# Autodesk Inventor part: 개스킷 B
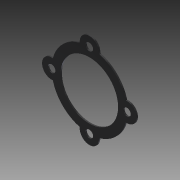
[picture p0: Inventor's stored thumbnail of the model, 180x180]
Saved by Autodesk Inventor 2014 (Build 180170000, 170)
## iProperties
Created: 2020-03
Part Number: 개스킷 B
Material: 고무
Document SubType Name: Modeling
Designer: mduedu
Density: 0.93 g/cm^3
Mass: 1.13966 g
Surface Area: 28.6179 cm^2
Volume: 1.22544 cm^3
Appearance: 고무 - 검은색 - 버전 1.1
Author: mduedu
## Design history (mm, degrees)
sketch "스케치1" dims "d1" = 55
  geometry: C1 r 21 at (0, 0); C2 r 7 at (0, 27.5); C3 r 7 at (-23.816, -13.75); C4 r 7 at (23.816, -13.75); 2 further points
  constraints: 4 centre point, 2 coincident, 2 vertical alignment, 9 other
  dimensions: "d0" = 42 diameter of C1; "d2" = 14 diameter of C2; "d5" = 360 deg dimension on point (0, 0) C2.centre (derived)
extrude "돌출1" new body sketch "스케치1" distance "d7" = 1; taper "d8" = 0 deg
extrude "돌출3" join sketch "스케치1" stored distance "d19" = 10; taper "d20" = 0 deg
fillet "모깎기1" dims "d11" = 1
extrude "돌출2" cut sketch "스케치1" stored distance "d9" = 1; taper "d10" = 0 deg
sketch "스케치2"
  geometry: C1 r 21 at (0, 0) reference; A1 r 7 centre (0, 27.5) between (6.999, 27.373) and (-6.999, 27.373) reference; A2 r 27.5 centre (0, 0) between (26.609, 6.943) and (7.718, 26.395) reference; A3 r 1 centre (7.999, 27.355) between (6.999, 27.373) and (7.718, 26.395) reference; A4 r 7 centre (0, 27.5) between (6.999, 27.373) and (-6.999, 27.373) reference; A5 r 1 centre (-7.999, 27.355) between (-7.718, 26.395) and (-6.999, 27.373) reference; A6 r 7 centre (0, -27.5) between (-6.943, -26.609) and (6.943, -26.609) reference; A7 r 7 centre (-27.5, 0) between (-26.609, 6.943) and (-26.609, -6.943) reference; A8 r 7 centre (27.5, 0) between (26.609, -6.943) and (26.609, 6.943) reference; A9 r 27.5 centre (0, 0) between (-26.609, -6.943) and (-6.943, -26.609) reference; A10 r 27.5 centre (0, 0) between (6.943, -26.609) and (26.609, -6.943) reference; A11 r 27.5 centre (0, 0) between (-7.718, 26.395) and (-26.609, 6.943) reference; 4 further points
hole "구멍1" sketch "스케치2" diameter "d12" = 5.5; stored, may be unused: countersink angle "d16" = 90 deg, drill point angle "d18" = 118 deg; dims "d13" = 6, "d14" = 4, "d15" = 2, "d17" = 8
node "솔리드1"
pattern_circular "원형 패턴1" dims angle "d22" = 360 deg
node "투영된 루프1"
